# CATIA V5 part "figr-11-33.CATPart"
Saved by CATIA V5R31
Part number: Part1
Bounding box of the stored display mesh (mm): x -120 to 40, y -443 to 443, z -443 to 443
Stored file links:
  D:\PROJECTS\Project 2021\US EDITION\CATIA V5 6R 2021\Resources\Part Files\c11_catia_v5_6r2021_prt\figr-11-33.CATPart
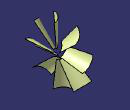
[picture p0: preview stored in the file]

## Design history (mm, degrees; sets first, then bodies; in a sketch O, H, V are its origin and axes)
Set1
  Plane1: type Offset, RefPlane xy-plane, Offset 443
  Sketch1 on Plane1, origin (0, 0, 443), H (1, 0, 0), V (0, 1, 0)
    arc A1 centre (51.3551, -160.9813) radius 171.358 from (40, 10) to (-120, -160) ccw
  Loft1: Sections (Sketch3; Sketch1)
  Sketch2 on zx-plane, origin (0, 0, 0), H (-1, 0, 0), V (0, 0, 1)
    line L1 (-270, 0) -> (280, 0)
    point P1 (-270, 0)
    coincidence: P1 H
    horizontal: L1 H
  Rotate1: ToTransfor Loft1, Axis Sketch2, Angle 45
  Rotate2: ToTransfor Loft1, Axis Sketch2, Angle 90 {= Rotate1.Angle * 2}
  Rotate3: ToTransfor Loft1, Axis Sketch2, Angle 135 {= Rotate1.Angle * 3}
  Rotate4: ToTransfor Loft1, Axis Sketch2, Angle 180 {= Rotate1.Angle * 4}
  Rotate5: ToTransfor Loft1, Axis Sketch2, Angle 225 {= Rotate1.Angle * 5}
  Rotate6: ToTransfor Loft1, Axis Sketch2, Angle 270 {= Rotate1.Angle * 6}
  Rotate7: ToTransfor Loft1, Axis Sketch2, Angle 315 {= Rotate1.Angle * 7}
  Rotate8: ToTransfor Loft1, Axis Sketch2, Angle 360 {= Rotate1.Angle * 8}
  Rotate9: ToTransfor Loft1, Axis Sketch2, Angle 405 {= Rotate1.Angle * 9}
Body1 (main body)
  Sketch3 on Plane2, origin (0, 0, 67), H (1, 0, 0), V (0, 1, 0)
    point P1 (-100, 0)
    arc A1 centre (50, -150) radius 158.1139 from (0, 0) to (-100, -100) ccw
Set2
  Plane2: type Offset, RefPlane xy-plane, Offset 67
